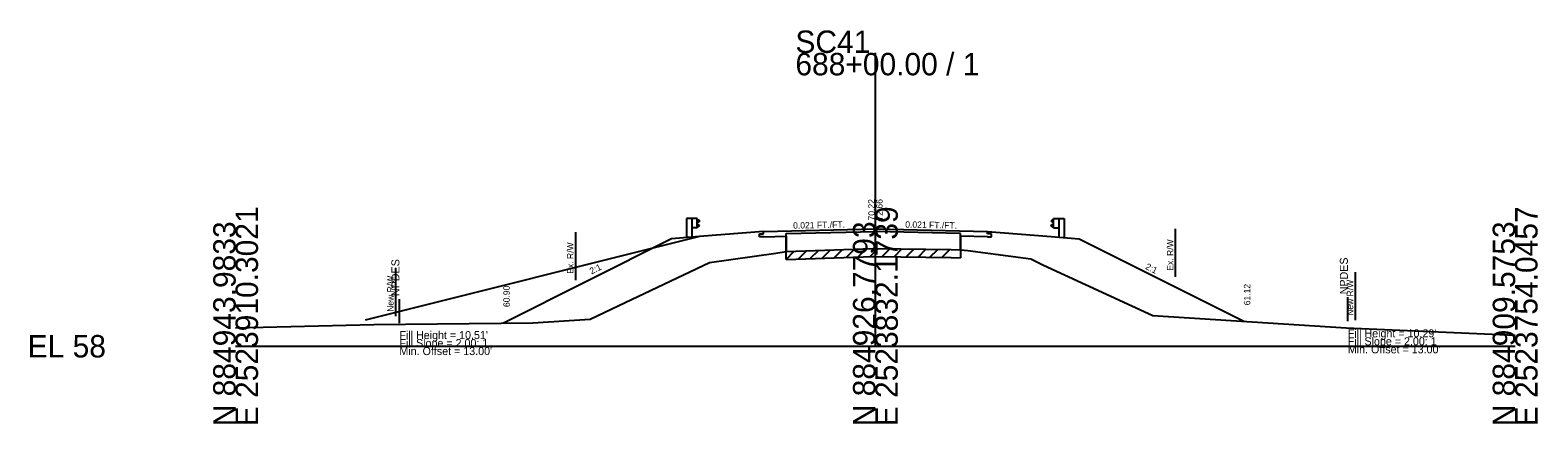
# Model space of a CAD drawing. Extents: x -26 to 183, y -10 to 24021.
# Drawn here: x -25.7 to 162.8, y 15990.3 to 16039.5 of the extents above; entities that cross this region are included whole.
import ezdxf

# ---------------------------------------------------------------- set-up
doc = ezdxf.new("R2010")
doc.units = 0
for name, color, linetype in [('RD_GPK_XS_Cell', 7, 'Continuous'), ('RD_XS_Base', 7, 'Continuous'), ('RD_XS_Buildup', 7, 'Continuous'), ('RD_XS_EarthShd', 7, 'Continuous'), ('RD_XS_ExGround', 7, 'Continuous'), ('RD_XS_ExPaveRet', 7, 'Continuous'), ('RD_XS_ExRW', 7, 'Continuous'), ('RD_XS_GR', 7, 'Continuous'), ('RD_XS_NewRW', 7, 'Continuous'), ('RD_XS_NPDES', 7, 'Continuous'), ('RD_XS_Pave', 7, 'Continuous'), ('RD_XS_TieSlope', 7, 'Continuous'), ('RD_XS_TX_Elev_EX', 7, 'Continuous'), ('RD_XS_TX_Elev_PR', 7, 'Continuous'), ('RD_XS_TX_Slope', 7, 'Continuous'), ('RD_XS_TX_Warning', 7, 'Continuous')]:
    doc.layers.add(name, color=color, linetype=linetype)

msp = doc.modelspace()

# ---------------------------------------------------------------- linework, layer by layer
at = {"layer": 'RD_GPK_XS_Cell'}
for p, q in [((80, 16000), (80, 16036.66)), ((0, 16000), (80, 16000)), ((80, 16000), (160, 16000))]:
    msp.add_line(p, q, dxfattribs=at)
at = {"layer": 'RD_XS_Base'}
for p, q in [((66, 16013.68), (68.83, 16013.74)), ((68.83, 16013.74), (68.83, 16011.85)), ((90.63, 16013.75), (90.63, 16012.06)), ((94, 16013.68), (90.63, 16013.75))]:
    msp.add_line(p, q, dxfattribs=at)
at = {"layer": 'RD_XS_Buildup'}
for p, q in [((68.83, 16014.1), (80, 16014.34)), ((68.83, 16011.85), (68.83, 16014.1)), ((90.63, 16014.11), (80, 16014.34)), ((90.63, 16012.06), (90.63, 16014.11))]:
    msp.add_line(p, q, dxfattribs=at)
at = {"layer": 'RD_XS_EarthShd'}
for p, q in [((66, 16014.36), (58, 16013.7)), ((94, 16014.36), (102, 16013.7)), ((58, 16013.7), (54.5, 16013.41)), ((102, 16013.7), (105.5, 16013.41))]:
    msp.add_line(p, q, dxfattribs=at)
at = {"layer": 'RD_XS_ExGround'}
for p, q in [((70.07, 16011.89), (79.69, 16012.22)), ((79.69, 16012.22), (80, 16012.22)), ((80, 16012.22), (89.47, 16012.08)), ((89.47, 16012.08), (90.63, 16012.06)), ((47.05, 16004.69), (59.27, 16010.48)), ((59.27, 16010.48), (67.57, 16011.64)), ((67.57, 16011.64), (68.83, 16011.85)), ((68.83, 16011.85), (70.07, 16011.89)), ((90.63, 16012.06), (91.55, 16011.95)), ((91.55, 16011.95), (99.43, 16010.91)), ((99.43, 16010.91), (101.01, 16010.13)), ((101.01, 16010.13), (114.71, 16003.83)), ((44.34, 16003.39), (47.05, 16004.69)), ((0, 16002.3), (17.27, 16002.72)), ((17.27, 16002.72), (37.15, 16002.93)), ((37.15, 16002.93), (44.34, 16003.39)), ((114.71, 16003.83), (138.87, 16002.31)), ((138.87, 16002.31), (160, 16001.39))]:
    msp.add_line(p, q, dxfattribs=at)
at = {"layer": 'RD_XS_ExPaveRet'}
for p, q in [((74.83, 16011.05), (75.87, 16012.09)), ((76.33, 16011.1), (77.37, 16012.14)), ((77.83, 16011.16), (78.87, 16012.19)), ((79.33, 16011.21), (80.33, 16012.21)), ((80.83, 16011.2), (81.82, 16012.19)), ((82.33, 16011.18), (83.32, 16012.17)), ((83.83, 16011.16), (84.82, 16012.15)), ((85.33, 16011.14), (86.32, 16012.13)), ((86.83, 16011.12), (87.82, 16012.1)), ((88.33, 16011.1), (89.32, 16012.08)), ((68.83, 16010.85), (69.86, 16011.88)), ((68.83, 16010.85), (68.83, 16011.85)), ((68.83, 16010.85), (70.07, 16010.89)), ((70.07, 16010.89), (79.69, 16011.22)), ((70.33, 16010.9), (71.37, 16011.93)), ((71.83, 16010.95), (72.87, 16011.98)), ((73.33, 16011), (74.37, 16012.04)), ((79.69, 16011.22), (80, 16011.22)), ((80, 16011.22), (89.47, 16011.08)), ((89.47, 16011.08), (90.63, 16011.06)), ((90.63, 16012.06), (90.63, 16011.06))]:
    msp.add_line(p, q, dxfattribs=at)
at = {"layer": 'RD_XS_ExRW'}
for p, q in [((42.5, 16014.27), (42.5, 16008.27)), ((117.5, 16014.66), (117.5, 16008.66))]:
    msp.add_line(p, q, dxfattribs=at)
at = {"layer": 'RD_XS_GR'}
for p, q in [((56.4, 16015.95), (56.4, 16013.56)), ((57.06, 16015.95), (56.4, 16015.95)), ((57.06, 16015.95), (57.06, 16013.62)), ((57.73, 16015.95), (57.06, 16015.95)), ((57.73, 16014.78), (57.73, 16015.95)), ((57.73, 16015.87), (58, 16015.67)), ((102.27, 16015.87), (102, 16015.67)), ((102.27, 16014.78), (102.27, 16015.95)), ((102.27, 16015.95), (102.94, 16015.95)), ((102.94, 16015.95), (102.94, 16013.62)), ((102.94, 16015.95), (103.6, 16015.95)), ((103.6, 16015.95), (103.6, 16013.56)), ((57.73, 16014.78), (57.06, 16014.78)), ((58, 16015.62), (57.73, 16015.42)), ((58, 16015.1), (57.73, 16015.3)), ((57.73, 16014.85), (58, 16015.05)), ((58, 16015.67), (58, 16015.62)), ((58, 16015.05), (58, 16015.1)), ((102, 16015.67), (102, 16015.62)), ((102, 16015.62), (102.27, 16015.42)), ((102, 16015.1), (102.27, 16015.3)), ((102, 16015.05), (102, 16015.1)), ((102.27, 16014.85), (102, 16015.05)), ((102.27, 16014.78), (102.94, 16014.78))]:
    msp.add_line(p, q, dxfattribs=at)
at = {"layer": 'RD_XS_NewRW'}
for p, q in [((20, 16009.75), (20, 16003.75)), ((140, 16009.26), (140, 16003.26))]:
    msp.add_line(p, q, dxfattribs=at)
at = {"layer": 'RD_XS_NPDES'}
for p, q in [((20.48, 16002.9), (20.48, 16005.9)), ((139.08, 16003.12), (139.08, 16006.12))]:
    msp.add_line(p, q, dxfattribs=at)
at = {"layer": 'RD_XS_Pave'}
for p, q in [((65.5, 16014.03), (66, 16014.04)), ((65.5, 16013.67), (65.5, 16014.03)), ((66, 16014.36), (80, 16014.66)), ((66, 16014.04), (66, 16014.36)), ((80, 16014.66), (94, 16014.36)), ((94, 16014.04), (94, 16014.36)), ((94.5, 16014.03), (94, 16014.04)), ((94.5, 16013.67), (94.5, 16014.03)), ((58, 16013.7), (16.21, 16003.25)), ((66, 16013.68), (65.5, 16013.67)), ((94, 16013.68), (94.5, 16013.67))]:
    msp.add_line(p, q, dxfattribs=at)
at = {"layer": 'RD_XS_TieSlope'}
for p, q in [((54.5, 16013.41), (33.48, 16002.9)), ((105.5, 16013.41), (126.08, 16003.12))]:
    msp.add_line(p, q, dxfattribs=at)

# ---------------------------------------------------------------- texts
at = {"layer": 'RD_GPK_XS_Cell'}
for s, p in [('SC41', (70, 16036.66)), ('688+00.00 / 1', (70, 16033.86)), ('EL 58', (-26, 15998.6))]:
    msp.add_text(s, height=2.8, dxfattribs=at).set_placement(p)
for s, p in [('E 2523910.3021', (2.8, 15990)), ('E 2523832.1739', (82.8, 15990)), ('E 2523754.0457', (162.8, 15990)), ('N 884943.9833', (0, 15990)), ('N 884926.7793', (80, 15990)), ('N 884909.5753', (160, 15990))]:
    msp.add_text(s, height=2.8, rotation=90, dxfattribs=at).set_placement(p)
at = {"layer": 'RD_XS_ExRW'}
for p in [(42.25, 16009.06), (117.25, 16009.44)]:
    msp.add_text('Ex. R/W ', height=0.8, rotation=90, dxfattribs=at).set_placement(p)
at = {"layer": 'RD_XS_NewRW'}
for p in [(19.75, 16004.3), (139.75, 16003.8)]:
    msp.add_text('New R/W ', height=0.8, rotation=90, dxfattribs=at).set_placement(p)
at = {"layer": 'RD_XS_TX_Elev_EX'}
msp.add_text('70.22', height=0.8, rotation=90, dxfattribs=at).set_placement((79.9, 16015.72))
at = {"layer": 'RD_XS_TX_Elev_PR'}
for s, p in [('72.66', (80.9, 16015.72)), ('60.90', (34.28, 16004.9)), ('61.12', (126.88, 16005.12))]:
    msp.add_text(s, height=0.8, rotation=90, dxfattribs=at).set_placement(p)
at = {"layer": 'RD_XS_TX_Slope'}
for s, rotation, p in [('0.021 FT./FT.', 1.1916, (69.72, 16014.69)), ('0.021 FT./FT.', 358.8084, (83.73, 16014.83)), ('2:1', 26.5651, (44.51, 16008.97)), ('2:1', 333.4349, (113.69, 16009.7))]:
    msp.add_text(s, height=0.8, rotation=rotation, dxfattribs=at).set_placement(p)
at = {"layer": 'RD_XS_TX_Warning'}
for p in [(20.48, 16005.9), (139.08, 16006.12)]:
    msp.add_text(' NPDES', height=1, rotation=90, dxfattribs=at).set_placement(p)
for s, p in [("Fill Height = 10.51' ", (20.48, 16000.9)), ('Fill Slope = 2.00: 1', (20.48, 15999.9)), ("Fill Height = 10.29' ", (139.08, 16001.12)), ('Fill Slope = 2.00: 1', (139.08, 16000.12)), ("Min. Offset = 13.00' ", (20.48, 15998.9)), ("Min. Offset = 13.00' ", (139.08, 15999.12))]:
    msp.add_text(s, height=1, dxfattribs=at).set_placement(p)

doc.saveas('drawing.dxf')
